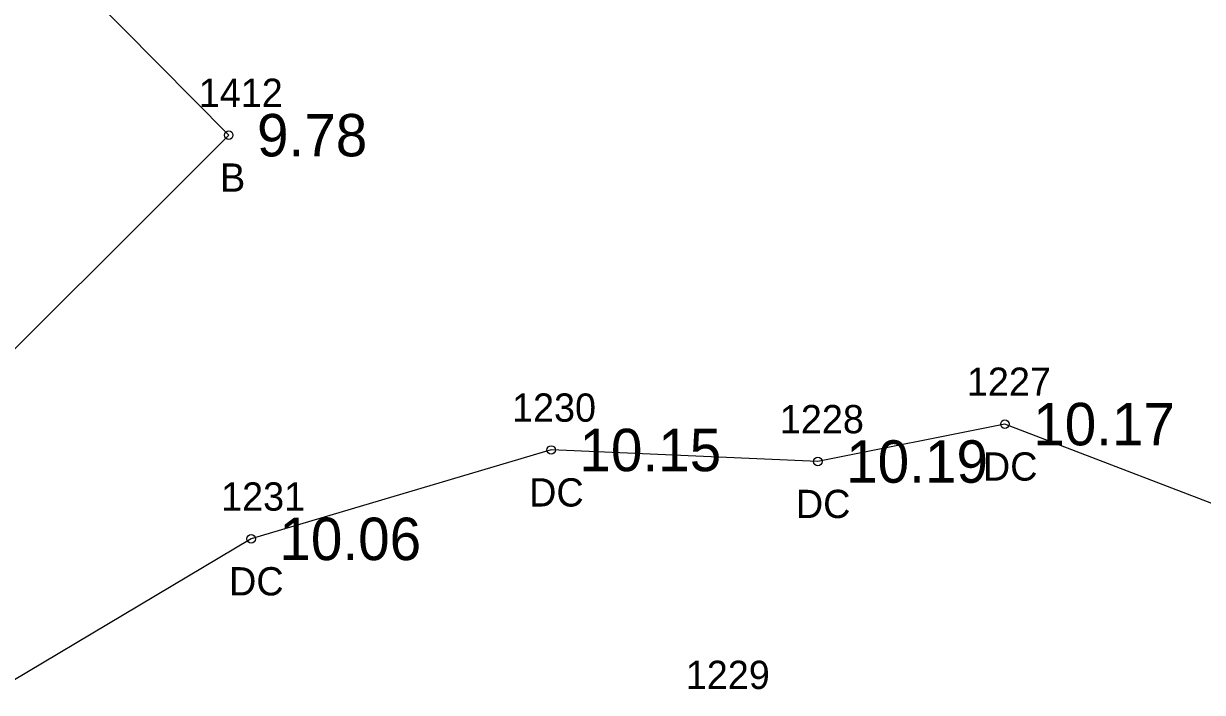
# Model space of a CAD drawing. Extents: x 2608598 to 2610682, y 641451 to 643526.
# Drawn here: x 2608949.52 to 2608991.25, y 643126.49 to 643150.15 of the extents above; entities that cross this region are included whole.
import ezdxf

# ---------------------------------------------------------------- set-up
doc = ezdxf.new("R2010")
doc.units = 0
for name, color, linetype in [('RD_EX_Bldg', 7, 'Continuous'), ('RD_EX_Bldg_txCode', 7, 'Continuous'), ('RD_EX_Conc', 7, 'Continuous'), ('RD_EX_Conc_txCode', 7, 'Continuous'), ('RD_EX_TX_Bldg_ELEV', 7, 'Continuous'), ('RD_EX_TX_Conc_ELEV', 7, 'Continuous'), ('RD_SMD_Locator', 7, 'Continuous')]:
    doc.layers.add(name, color=color, linetype=linetype)

msp = doc.modelspace()

# ---------------------------------------------------------------- linework, layer by layer
at = {"layer": 'RD_EX_Bldg'}
msp.add_lwpolyline([(2608921.816, 643181.484), (2608956.787, 643146.205), (2608904.138, 643093.65), (2608869.167, 643128.93), (2608921.816, 643181.484)], dxfattribs=at)
at = {"layer": 'RD_EX_Conc'}
msp.add_lwpolyline([(2609024.85, 643112.937), (2609016.081, 643116.287), (2609004.891, 643123.888), (2608993.796, 643132.322), (2608984.26, 643135.984), (2608977.639, 643134.66), (2608968.198, 643135.068), (2608957.578, 643131.923), (2608944.582, 643124.187), (2608938.749, 643122.143), (2608934.116, 643122.552)], dxfattribs=at)
at = {"layer": 'RD_SMD_Locator'}
for centre in [(2608956.787, 643146.205), (2608984.26, 643135.984), (2608968.198, 643135.068), (2608977.639, 643134.66), (2608957.578, 643131.923)]:
    msp.add_circle(centre, 0.15, dxfattribs=at)

# ---------------------------------------------------------------- texts
at = {"layer": 'RD_EX_Bldg_txCode'}
for s, p in [('1412', (2608955.724, 643147.205)), ('B', (2608956.479, 643144.205))]:
    msp.add_text(s, height=1, dxfattribs=at).set_placement(p)
at = {"layer": 'RD_EX_Conc_txCode'}
for s, p in [('1227', (2608982.913, 643136.984)), ('1230', (2608966.812, 643136.068)), ('1228', (2608976.293, 643135.66)), ('DC', (2608983.48, 643133.984)), ('DC', (2608967.419, 643133.068)), ('1231', (2608956.515, 643132.923)), ('DC', (2608976.86, 643132.66)), ('DC', (2608956.798, 643129.923)), ('1229', (2608972.963, 643126.613))]:
    msp.add_text(s, height=1, dxfattribs=at).set_placement(p)
at = {"layer": 'RD_EX_TX_Bldg_ELEV'}
msp.add_text('9.78', height=1.5, dxfattribs=at).set_placement((2608957.787, 643145.455))
at = {"layer": 'RD_EX_TX_Conc_ELEV'}
for s, p in [('10.17', (2608985.26, 643135.234)), ('10.15', (2608969.198, 643134.318)), ('10.19', (2608978.639, 643133.91)), ('10.06', (2608958.578, 643131.173))]:
    msp.add_text(s, height=1.5, dxfattribs=at).set_placement(p)

doc.saveas('drawing.dxf')
